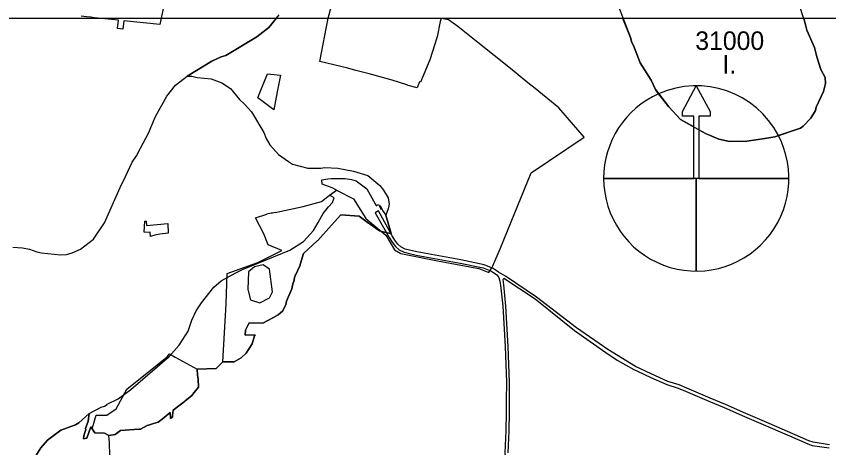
# Model space of a CAD drawing. Extents: x -555509 to -553014, y -1186753 to -1182560.
# Drawn here: x -554443 to -553565, y -1184728 to -1184262 of the extents above; entities that cross this region are included whole.
import ezdxf

# ---------------------------------------------------------------- set-up
doc = ezdxf.new("R2010")
doc.units = 0
for name, color, linetype in [('I_2_Leg_HV', 7, 'Continuous'), ('LEG_6_ZPF', 7, 'Continuous'), ('Level 29', 7, 'Continuous'), ('Level 52', 7, 'Continuous'), ('pěší_tr', 7, 'Continuous'), ('ZPF_I_TR_OCHRANY', 7, 'Continuous')]:
    doc.layers.add(name, color=color, linetype=linetype)

msp = doc.modelspace()

# ---------------------------------------------------------------- linework, layer by layer
at = {"layer": 'I_2_Leg_HV'}
msp.add_line((-554175.99, -1184530.83), (-554185.52, -1184532.76), dxfattribs=at)
for points in [[(-554185.52, -1184532.76), (-554191.94, -1184538.21), (-554192.58, -1184557.37), (-554189.9, -1184568.29), (-554179.74, -1184571.5)], [(-554179.74, -1184571.5), (-554169.14, -1184566.25), (-554166.14, -1184559.72), (-554169.14, -1184535.43), (-554175.99, -1184530.83)]]:
    msp.add_lwpolyline(points, dxfattribs=at)
at = {"layer": 'LEG_6_ZPF'}
for p, q in [((-554161.89, -1184264.77), (-554966.48, -1184264.77)), ((-553787.59, -1184264.77), (-554161.89, -1184264.77)), ((-553535.77, -1184264.77), (-553592.38, -1184264.77)), ((-554216.44, -1184304.63), (-554182.94, -1184284.75)), ((-553776.38, -1184294), (-553778.06, -1184290.62)), ((-553752.62, -1184341.5), (-553757.31, -1184331.38)), ((-553749.08, -1184346.08), (-553752.62, -1184341.5)), ((-553738.19, -1184360.13), (-553749.08, -1184346.08)), ((-553711.1, -1184437.44), (-553711.1, -1184381.91)), ((-553705.77, -1184384.93), (-553705.77, -1184437.44)), ((-553705.77, -1184384.93), (-553705.77, -1184437.44)), ((-553683.94, -1184395), (-553694.12, -1184390.75)), ((-553683.94, -1184395), (-553694.12, -1184390.75)), ((-553623.75, -1184392.38), (-553634.31, -1184394.5)), ((-553623.75, -1184392.38), (-553634.31, -1184394.5)), ((-553619.84, -1184391.08), (-553623.75, -1184392.38)), ((-553619.84, -1184391.08), (-553623.75, -1184392.38)), ((-553634.31, -1184394.5), (-553653.81, -1184397.13)), ((-553634.31, -1184394.5), (-553653.81, -1184397.13)), ((-553808.44, -1184437.44), (-553808.44, -1184437.44)), ((-553808.44, -1184437.44), (-553808.44, -1184437.44)), ((-553711.1, -1184437.44), (-553808.44, -1184437.44)), ((-553808.44, -1184437.44), (-553711.1, -1184437.44)), ((-553711.1, -1184437.44), (-553808.44, -1184437.44)), ((-553708.44, -1184437.44), (-553711.1, -1184437.44)), ((-553708.44, -1184437.44), (-553711.1, -1184437.44)), ((-553705.77, -1184437.44), (-553708.44, -1184437.44)), ((-553708.44, -1184437.44), (-553708.44, -1184537.44)), ((-553708.44, -1184537.44), (-553708.44, -1184437.44)), ((-553705.77, -1184437.44), (-553708.44, -1184437.44)), ((-553708.44, -1184437.44), (-553708.44, -1184537.44)), ((-553708.44, -1184537.44), (-553708.44, -1184437.44)), ((-553705.77, -1184437.44), (-553608.44, -1184437.44)), ((-553608.44, -1184437.44), (-553705.77, -1184437.44)), ((-553705.77, -1184437.44), (-553608.44, -1184437.44)), ((-553608.44, -1184437.44), (-553705.77, -1184437.44))]:
    msp.add_line(p, q, dxfattribs=at)
for points in [[(-554161.89, -1184264.77), (-554169.81, -1184274.5), (-554182.94, -1184284.75), (-554216.44, -1184304.63), (-554221.56, -1184306.38), (-554231.31, -1184311), (-554258, -1184327.12)], [(-554182.94, -1184284.75), (-554169.81, -1184274.5), (-554161.89, -1184264.77)], [(-553778.06, -1184290.62), (-553779.31, -1184285.5), (-553787.59, -1184264.77)], [(-553592.38, -1184264.77), (-553591.5, -1184267.38), (-553588.94, -1184277.5), (-553580.94, -1184296.13), (-553578.38, -1184306.38), (-553574.12, -1184319.88)], [(-553757.31, -1184331.38), (-553769.12, -1184312.75), (-553776.38, -1184294)], [(-554258, -1184327.12), (-554231.31, -1184311), (-554221.56, -1184306.38), (-554216.44, -1184304.63)], [(-553574.12, -1184319.88), (-553569.44, -1184328.38), (-553569.06, -1184335.12), (-553571.19, -1184343.62), (-553579.19, -1184360.63)], [(-554446.25, -1184511.5), (-554436.06, -1184512.38), (-554428.44, -1184513.62), (-554420.38, -1184516.62), (-554415.31, -1184517.88), (-554394.94, -1184520), (-554388.56, -1184519.63), (-554382.25, -1184517.88), (-554373.31, -1184513.62), (-554359.31, -1184503), (-554347.44, -1184485.25), (-554330.5, -1184447.12), (-554324.56, -1184435.25), (-554317.38, -1184420), (-554312.69, -1184413.13), (-554308.44, -1184404.75), (-554299.56, -1184387.75), (-554297.44, -1184382.62), (-554292.38, -1184370.75), (-554280.06, -1184348.75), (-554270.75, -1184336.88), (-554258, -1184327.12)], [(-554258, -1184327.12), (-554252.94, -1184327.12), (-554247.38, -1184328.38), (-554232.12, -1184330.12), (-554220.69, -1184334.38), (-554211.38, -1184340.25), (-554201.62, -1184352.13), (-554196.12, -1184357.25), (-554188.5, -1184365.75), (-554175.31, -1184387.75), (-554172.75, -1184394.5), (-554168.94, -1184401.25), (-554159.62, -1184411.5), (-554148.62, -1184419.12), (-554144.38, -1184422.13), (-554127.81, -1184426.38), (-554113.88, -1184426.38), (-554109.62, -1184425.5), (-554095.62, -1184426.38), (-554078.69, -1184429.75), (-554063, -1184434.38), (-554050.25, -1184445), (-554046, -1184450), (-554040.94, -1184458.5), (-554040.06, -1184465.38), (-554040.94, -1184470.38), (-554043.5, -1184477.25)], [(-553711.1, -1184381.91), (-553725.5, -1184373.75), (-553738.19, -1184360.13)], [(-553579.19, -1184360.63), (-553579.62, -1184364), (-553584.75, -1184372.5), (-553593.19, -1184381), (-553595.75, -1184383.12), (-553619.84, -1184391.08)], [(-553694.12, -1184390.75), (-553697.94, -1184389.38), (-553705.77, -1184384.93)], [(-553694.12, -1184390.75), (-553697.94, -1184389.38), (-553705.77, -1184384.93)], [(-553653.81, -1184397.13), (-553672.5, -1184397.5), (-553683.94, -1184395)], [(-553653.81, -1184397.13), (-553672.5, -1184397.5), (-553683.94, -1184395)], [(-554043.5, -1184477.25), (-554037.94, -1184496.75), (-554042.19, -1184496.25), (-554050.51, -1184493.92), (-554052.62, -1184492.42), (-554060.61, -1184486.74), (-554060.73, -1184486.66), (-554062.12, -1184485.63), (-554062.25, -1184485.58), (-554072.51, -1184478.29), (-554092.26, -1184476.84), (-554102.24, -1184487.86), (-554117.12, -1184504.29), (-554117.62, -1184504.84), (-554132.53, -1184518.35), (-554136.01, -1184530.22), (-554136.28, -1184531.16), (-554141.64, -1184542.54), (-554142.08, -1184544.47), (-554143.12, -1184548.98), (-554143.5, -1184549.75), (-554145.25, -1184556.5), (-554150.75, -1184570), (-554151.56, -1184573.5), (-554155, -1184580.25), (-554159.8, -1184584.63), (-554165.66, -1184587.76), (-554176.53, -1184593.57), (-554191.34, -1184593.33), (-554195.16, -1184601.3), (-554195.61, -1184606.4), (-554184.55, -1184606.21), (-554185.5, -1184607.38), (-554188.06, -1184615.88), (-554194.38, -1184626), (-554199.94, -1184631.12), (-554207.3, -1184635.19), (-554219.51, -1184635.3), (-554226.98, -1184642.35), (-554247.47, -1184643.35), (-554246.78, -1184649.63), (-554246.31, -1184654.17), (-554245.93, -1184662.76), (-554250.51, -1184668.31), (-554253.15, -1184671.5), (-554260.66, -1184677.77), (-554261.49, -1184678.42), (-554267.01, -1184682.66), (-554273.25, -1184687.46), (-554273.94, -1184693.19), (-554273.83, -1184695.06), (-554274.56, -1184695.5), (-554276.06, -1184696.3), (-554276.41, -1184689.96), (-554285.24, -1184697.05), (-554289.4, -1184700.39), (-554294.55, -1184701.98), (-554299.98, -1184703.66), (-554301.21, -1184704.05), (-554308.51, -1184707.78), (-554309.96, -1184707.89), (-554315.2, -1184708.27), (-554330.24, -1184709.56), (-554335.95, -1184713.64), (-554342.58, -1184714.8), (-554347.4, -1184712.36), (-554357.64, -1184711.84), (-554362.22, -1184705.44), (-554366.54, -1184717.58), (-554369.94, -1184718.5), (-554369.74, -1184715.16), (-554368.47, -1184711.54), (-554367.35, -1184708.34), (-554367.95, -1184707.27), (-554364.88, -1184699.38), (-554364, -1184690.88)], [(-554364, -1184690.88), (-554375, -1184701), (-554378.81, -1184703.12), (-554394.5, -1184709.13), (-554408.94, -1184719.75), (-554416.12, -1184728.25), (-554421.62, -1184736.63), (-554424.62, -1184743.5), (-554435.25, -1184755.38), (-554440.75, -1184760.38), (-554447.94, -1184767.25), (-554469.56, -1184779.5), (-554542.5, -1184810.5), (-554566.62, -1184818.5), (-554606.06, -1184833.38), (-554611.62, -1184835.88), (-554626.88, -1184837.12)]]:
    msp.add_lwpolyline(points, dxfattribs=at)
for start_param, end_param in [(1.989297, 3.141557), (1.989297, 3.141557), (3.141557, 6.76526), (3.141557, 6.76526), (3.141557, 6.76526)]:
    msp.add_ellipse((-553708.44, -1184437.44), major_axis=(100, 0), ratio=0.99999, start_param=start_param, end_param=end_param, dxfattribs=at)
at = {"layer": 'Level 29'}
for points in [[(-553793.31, -1184250), (-553788.25, -1184263.13), (-553779.31, -1184285.5), (-553778.06, -1184290.62), (-553776.38, -1184294), (-553769.12, -1184312.75), (-553757.31, -1184331.38), (-553752.62, -1184341.5), (-553738.19, -1184360.13), (-553725.5, -1184373.75), (-553697.94, -1184389.38), (-553694.12, -1184390.75), (-553683.94, -1184395), (-553672.5, -1184397.5), (-553653.81, -1184397.13), (-553634.31, -1184394.5), (-553623.75, -1184392.38), (-553595.75, -1184383.12), (-553593.19, -1184381), (-553584.75, -1184372.5), (-553579.62, -1184364), (-553579.19, -1184360.63), (-553571.19, -1184343.62), (-553569.06, -1184335.12), (-553569.44, -1184328.38), (-553574.12, -1184319.88), (-553578.38, -1184306.38), (-553580.94, -1184296.13), (-553588.94, -1184277.5), (-553591.5, -1184267.38), (-553597.88, -1184248.63)], [(-554258, -1184327.12), (-554231.31, -1184311), (-554221.56, -1184306.38), (-554216.44, -1184304.63), (-554182.94, -1184284.75), (-554169.81, -1184274.5), (-554158.81, -1184261)], [(-554446.25, -1184511.5), (-554436.06, -1184512.38), (-554428.44, -1184513.62), (-554420.38, -1184516.62), (-554415.31, -1184517.88), (-554394.94, -1184520), (-554388.56, -1184519.63), (-554382.25, -1184517.88), (-554373.31, -1184513.62), (-554359.31, -1184503), (-554347.44, -1184485.25), (-554330.5, -1184447.12), (-554324.56, -1184435.25), (-554317.38, -1184420), (-554312.69, -1184413.13), (-554308.44, -1184404.75), (-554299.56, -1184387.75), (-554297.44, -1184382.62), (-554292.38, -1184370.75), (-554280.06, -1184348.75), (-554270.75, -1184336.88), (-554258, -1184327.12)], [(-554258, -1184327.12), (-554252.94, -1184327.12), (-554247.38, -1184328.38), (-554232.12, -1184330.12), (-554220.69, -1184334.38), (-554211.38, -1184340.25), (-554201.62, -1184352.13), (-554196.12, -1184357.25), (-554188.5, -1184365.75), (-554175.31, -1184387.75), (-554172.75, -1184394.5), (-554168.94, -1184401.25), (-554159.62, -1184411.5), (-554148.62, -1184419.12), (-554144.38, -1184422.13), (-554127.81, -1184426.38), (-554113.88, -1184426.38), (-554109.62, -1184425.5), (-554095.62, -1184426.38), (-554078.69, -1184429.75), (-554063, -1184434.38), (-554050.25, -1184445), (-554046, -1184450), (-554040.94, -1184458.5), (-554040.06, -1184465.38), (-554040.94, -1184470.38), (-554043.5, -1184477.25)], [(-554364, -1184690.88), (-554350.99, -1184684.4), (-554347.38, -1184683.02), (-554344.41, -1184681.42), (-554344.37, -1184681.1), (-554332.62, -1184675.25), (-554319.06, -1184665), (-554277.5, -1184629.38), (-554266.88, -1184617.5), (-554257.12, -1184602.25), (-554252.94, -1184590.38), (-554248.25, -1184580.25), (-554242.75, -1184571.75), (-554229.19, -1184554.75), (-554221.56, -1184548), (-554206.25, -1184539.5), (-554198.25, -1184535.75), (-554147.31, -1184514.88), (-554132.5, -1184505.63), (-554121.88, -1184493.75), (-554116.84, -1184484.87), (-554111.31, -1184475.13), (-554105.38, -1184468.21), (-554105.35, -1184468.18), (-554101.12, -1184463.25), (-554099.44, -1184458.5), (-554104.53, -1184455.61), (-554096.79, -1184449.95), (-554101.44, -1184447.55), (-554112.29, -1184443.79), (-554112.56, -1184439), (-554106.39, -1184437.97), (-554102.81, -1184437.38), (-554087.56, -1184437.38), (-554080.53, -1184438.68), (-554080.52, -1184438.68), (-554075.6, -1184440.19), (-554064.28, -1184448.61), (-554055.15, -1184464.96), (-554054.22, -1184466.62), (-554054.03, -1184466.97), (-554051.58, -1184465.63), (-554048.74, -1184470.8), (-554049.74, -1184466.72), (-554047.31, -1184472.12), (-554043.5, -1184477.25)], [(-554364, -1184690.88), (-554364.88, -1184699.38), (-554367.95, -1184707.27), (-554367.35, -1184708.34), (-554368.47, -1184711.54), (-554369.74, -1184715.16), (-554369.94, -1184718.5), (-554366.54, -1184717.58), (-554362.22, -1184705.44), (-554357.64, -1184711.84), (-554347.4, -1184712.36), (-554342.58, -1184714.8), (-554335.95, -1184713.64), (-554330.24, -1184709.56), (-554315.2, -1184708.27), (-554309.96, -1184707.89), (-554308.51, -1184707.78), (-554301.21, -1184704.05), (-554299.98, -1184703.66), (-554294.55, -1184701.98), (-554289.4, -1184700.39), (-554285.24, -1184697.05), (-554276.41, -1184689.96), (-554276.06, -1184696.3), (-554274.56, -1184695.5), (-554273.83, -1184695.06), (-554273.94, -1184693.19), (-554273.25, -1184687.46), (-554267.01, -1184682.66), (-554261.49, -1184678.42), (-554260.66, -1184677.77), (-554253.15, -1184671.5), (-554250.51, -1184668.31), (-554245.93, -1184662.76), (-554246.31, -1184654.17), (-554246.78, -1184649.63), (-554247.47, -1184643.35), (-554226.98, -1184642.35), (-554219.51, -1184635.3), (-554207.3, -1184635.19), (-554199.94, -1184631.12), (-554194.38, -1184626), (-554188.06, -1184615.88), (-554185.5, -1184607.38), (-554184.55, -1184606.21), (-554195.61, -1184606.4), (-554195.16, -1184601.3), (-554191.34, -1184593.33), (-554176.53, -1184593.57), (-554165.66, -1184587.76), (-554159.8, -1184584.63), (-554155, -1184580.25), (-554151.56, -1184573.5), (-554150.75, -1184570), (-554145.25, -1184556.5), (-554143.5, -1184549.75), (-554143.12, -1184548.98), (-554142.08, -1184544.47), (-554141.64, -1184542.54), (-554136.28, -1184531.16), (-554136.01, -1184530.22), (-554132.53, -1184518.35), (-554117.62, -1184504.84), (-554117.12, -1184504.29), (-554102.24, -1184487.86), (-554092.26, -1184476.84), (-554072.51, -1184478.29), (-554062.25, -1184485.58), (-554062.12, -1184485.63), (-554060.73, -1184486.66), (-554060.61, -1184486.74), (-554052.62, -1184492.42), (-554050.51, -1184493.92), (-554042.19, -1184496.25), (-554037.94, -1184496.75), (-554043.5, -1184477.25)], [(-554626.88, -1184837.12), (-554611.62, -1184835.88), (-554606.06, -1184833.38), (-554566.62, -1184818.5), (-554542.5, -1184810.5), (-554469.56, -1184779.5), (-554447.94, -1184767.25), (-554440.75, -1184760.38), (-554435.25, -1184755.38), (-554424.62, -1184743.5), (-554421.62, -1184736.63), (-554416.12, -1184728.25), (-554408.94, -1184719.75), (-554394.5, -1184709.13), (-554378.81, -1184703.12), (-554375, -1184701), (-554364, -1184690.88)]]:
    msp.add_lwpolyline(points, dxfattribs=at)
at = {"layer": 'Level 52'}
for points in [[(-554283.44, -1184250.8), (-554287.72, -1184271.23), (-554326.33, -1184267.32), (-554327.43, -1184276.33), (-554333.44, -1184275.83), (-554332.24, -1184266.72), (-554358.07, -1184264.1), (-554362.22, -1184263.55), (-554366.82, -1184262.94), (-554372.66, -1184262.44)], [(-553856.94, -1184361.2), (-553882.23, -1184340.38), (-553890.19, -1184334.36), (-553909.03, -1184319), (-553944.41, -1184290.7), (-553965.73, -1184273.58), (-553975.95, -1184266.36), (-553983.89, -1184264.88), (-553984.98, -1184268.07), (-553988.28, -1184284.83), (-553996.23, -1184309.64), (-554006.09, -1184333.7), (-554007.16, -1184333.36), (-554009.7, -1184339.84), (-554019.38, -1184337.28), (-554021.12, -1184336.41), (-554036.96, -1184331.42), (-554061.51, -1184324.7), (-554076.01, -1184320.94), (-554084.8, -1184318.51), (-554114.73, -1184311.21), (-554105.98, -1184264.44), (-554102.32, -1184251.25)], [(-554179.3, -1184343.94), (-554171.45, -1184324.41), (-554157.37, -1184326.12), (-554159.45, -1184336.82), (-554160.88, -1184344.18), (-554164.66, -1184363.51), (-554181.77, -1184350.57), (-554179.3, -1184343.94)], [(-553920.04, -1184513.36), (-553908.23, -1184484.2), (-553886.58, -1184431.24), (-553829.38, -1184392.78), (-553856.94, -1184361.2)], [(-554163.2, -1184474.11), (-554133.03, -1184467.75), (-554113.17, -1184462.37), (-554106.24, -1184456.86), (-554096.79, -1184449.95)], [(-554099.56, -1184448.52), (-554096.79, -1184449.95), (-554078.37, -1184459.39), (-554065.08, -1184480.67), (-554043.73, -1184498.74), (-554034.15, -1184514.33), (-554027.42, -1184518.38), (-553985.89, -1184526.77), (-553983.73, -1184527.21), (-553943.3, -1184534.51), (-553932.52, -1184538.98), (-553929.16, -1184533.92), (-553928.84, -1184533.21), (-553928.26, -1184531.89), (-553920.04, -1184513.36)], [(-554216.08, -1184572.66), (-554214.89, -1184539.93), (-554181.64, -1184528.14), (-554156.08, -1184515.36), (-554170.58, -1184509.11), (-554175.48, -1184497.33), (-554184.23, -1184479.8), (-554171.95, -1184475.96)], [(-554163.2, -1184474.11), (-554166.16, -1184474.74), (-554167.45, -1184475.01), (-554171.95, -1184475.96)], [(-554302.1, -1184488.23), (-554279.04, -1184485.94), (-554278.79, -1184496.59), (-554287.71, -1184497.57), (-554292.86, -1184498.59), (-554297.67, -1184500.1), (-554298.19, -1184495.53), (-554299.48, -1184495.83), (-554304.39, -1184495.53), (-554303.75, -1184483.72), (-554302.55, -1184483.6), (-554302.1, -1184488.23)], [(-554277.24, -1184626.81), (-554271.13, -1184630.21), (-554247.47, -1184643.35), (-554226.98, -1184642.35), (-554219.51, -1184635.3), (-554216.08, -1184572.66)], [(-554347.4, -1184712.36), (-554357.64, -1184711.84), (-554360.55, -1184707.77), (-554356.21, -1184692.69), (-554344.83, -1184692.69), (-554334.59, -1184685.99), (-554323.09, -1184664.88), (-554279.6, -1184629.99), (-554277.24, -1184626.81)], [(-554341.75, -1184736.88), (-554341.86, -1184722.43), (-554342.58, -1184714.8), (-554347.4, -1184712.36)]]:
    msp.add_lwpolyline(points, dxfattribs=at)
at = {"layer": 'pěší_tr'}
for points in [[(-553564.63, -1184724.71), (-553582.35, -1184722.02), (-553586.79, -1184720.62), (-553595.79, -1184716.7), (-553629.85, -1184701.93), (-553655.08, -1184691.08), (-553676.99, -1184681.48), (-553693.45, -1184674.37), (-553718.82, -1184663.56), (-553726.8, -1184660.25), (-553739.29, -1184656.56), (-553757.17, -1184648.21), (-553774.16, -1184640.2), (-553803.8, -1184622.03), (-553837.69, -1184598.76), (-553881.11, -1184565.44), (-553914.41, -1184542.78), (-553921.94, -1184538.41), (-553927.81, -1184534.55), (-553937.63, -1184530.48), (-553962.79, -1184525.32), (-554010.12, -1184516.67), (-554022.76, -1184513.58), (-554027.3, -1184511.39), (-554030.73, -1184508.43), (-554034.06, -1184504.11), (-554036.93, -1184499.37), (-554051.55, -1184472.5), (-554055.16, -1184474.68), (-554039.92, -1184501.18), (-554036.95, -1184506.09), (-554033.29, -1184510.85), (-554029.23, -1184514.34), (-554023.95, -1184516.89), (-554010.85, -1184520.09), (-553963.45, -1184528.75), (-553938.66, -1184533.84), (-553929.46, -1184537.65), (-553923.87, -1184541.33), (-553921.74, -1184544.25), (-553920.7, -1184548.12), (-553919.7, -1184552.55), (-553917.46, -1184575.42), (-553914.88, -1184618.77)], [(-553911.55, -1184733.38), (-553911.34, -1184725.74), (-553910.43, -1184709.83), (-553910.18, -1184689.89), (-553910.26, -1184677.33), (-553910, -1184657.07), (-553911.38, -1184618.6), (-553913.97, -1184575.15), (-553916.21, -1184552.21), (-553917, -1184546.4), (-553916.19, -1184545.2), (-553882.3, -1184567.34), (-553839.83, -1184601.57), (-553806.23, -1184625.08), (-553793.89, -1184633.45), (-553775.8, -1184643.66), (-553771.93, -1184645.48), (-553757.59, -1184652.2), (-553740.28, -1184659.92), (-553727.96, -1184663.55), (-553720.18, -1184666.78), (-553694.83, -1184677.59), (-553678.39, -1184684.69), (-553656.47, -1184694.29), (-553631.24, -1184705.14), (-553597.18, -1184719.91), (-553588.02, -1184723.91), (-553583.15, -1184725.44), (-553565.13, -1184728.17)], [(-553914.88, -1184618.77), (-553913.5, -1184657.11), (-553913.76, -1184677.32), (-553913.68, -1184689.88), (-553913.93, -1184709.71), (-553914.84, -1184725.59), (-553915.05, -1184733.49), (-553911.52, -1184771.82), (-553908.33, -1184809.34)]]:
    msp.add_lwpolyline(points, dxfattribs=at)
at = {"layer": 'ZPF_I_TR_OCHRANY'}
for p, q in [((-553592.38, -1184264.77), (-553787.59, -1184264.77)), ((-553711.1, -1184381.91), (-553711.1, -1184370.14)), ((-553705.77, -1184370.14), (-553705.77, -1184384.93))]:
    msp.add_line(p, q, dxfattribs=at)
for points in [[(-553787.59, -1184264.77), (-553779.31, -1184285.5), (-553778.06, -1184290.62), (-553776.38, -1184294), (-553769.12, -1184312.75), (-553757.31, -1184331.38), (-553752.62, -1184341.5), (-553749.08, -1184346.08)], [(-553619.84, -1184391.08), (-553595.75, -1184383.12), (-553593.19, -1184381), (-553584.75, -1184372.5), (-553579.62, -1184364), (-553579.19, -1184360.63), (-553571.19, -1184343.62), (-553569.06, -1184335.12), (-553569.44, -1184328.38), (-553574.12, -1184319.88), (-553578.38, -1184306.38), (-553580.94, -1184296.13), (-553588.94, -1184277.5), (-553591.5, -1184267.38), (-553592.38, -1184264.77)], [(-553711.1, -1184370.14), (-553723.34, -1184370.14), (-553723.34, -1184365.24), (-553708.44, -1184337.45)], [(-553708.44, -1184337.45), (-553693.53, -1184365.24), (-553693.53, -1184370.14), (-553705.77, -1184370.14)], [(-553749.08, -1184346.08), (-553738.19, -1184360.13), (-553725.5, -1184373.75), (-553711.1, -1184381.91)], [(-553705.77, -1184384.93), (-553697.94, -1184389.38), (-553694.12, -1184390.75), (-553683.94, -1184395), (-553672.5, -1184397.5), (-553653.81, -1184397.13), (-553634.31, -1184394.5), (-553623.75, -1184392.38), (-553619.84, -1184391.08)]]:
    msp.add_lwpolyline(points, dxfattribs=at)
msp.add_ellipse((-553708.44, -1184437.44), major_axis=(100, 0), ratio=0.99999, start_param=0.482075, end_param=1.989297, dxfattribs=at)
msp.add_ellipse((-553708.44, -1184437.44), major_axis=(100, 0), ratio=0.99999, start_param=0.482075, end_param=1.989297, dxfattribs=at)

# ---------------------------------------------------------------- texts
at = {"layer": 'Level 29'}
for s, p in [('31000', (-553709.51, -1184298.81)), ('I.', (-553680.2, -1184324.26))]:
    msp.add_text(s, height=20, dxfattribs=at).set_placement(p)

doc.saveas('drawing.dxf')
